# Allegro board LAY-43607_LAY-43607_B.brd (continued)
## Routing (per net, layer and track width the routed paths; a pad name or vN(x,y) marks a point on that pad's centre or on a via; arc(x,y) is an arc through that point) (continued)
USB2_RX_P: length 61.4
  BOTTOM w0.132: v1(73.83,54.6) 74.14,54.91 arc(74.23,54.97) 74.34,54.99 74.6,54.99 arc(74.62,54.99) 74.64,54.99 74.96,54.99 arc(75.17,55.03) 75.36,55.16 arc(75.47,55.33) 75.51,55.54 75.51,55.87 arc(75.55,55.96) 75.65,56 75.94,56 arc(76.07,56.06) 76.13,56.19 76.13,56.35 arc(76.07,56.48) 75.94,56.53 75.65,56.53 arc(75.55,56.57) 75.51,56.66 75.51,56.92 arc(75.56,57.14) 75.68,57.33 89.65,71.34 arc(89.7,71.39) 89.75,71.45 91.12,72.98 92.75,74.8 arc(93.27,75.58) 93.45,76.49 93.45,80.03 arc(93.79,81.61) 94.72,82.93 96,84.14 arc(96.22,84.43) 96.33,84.77 arc(96.86,89.67) 97,94.6 arc(97.01,94.67) 97.02,94.73 U44.1 U44.10 97.17,96.59 arc(97.17,96.64) 97.14,96.68 97.09,96.73 arc(97.06,96.77) 97.05,96.82 97.05,96.95 arc(97.41,98.6) 98.43,99.94 arc(99.33,100.55) 100.34,100.94 arc(100.72,101.1) 101.05,101.36 101.34,101.65 arc(101.53,101.96) 101.57,102.32 101.57,102.44 arc(101.61,102.53) 101.71,102.57 J70.15
USB2_TX_N: length 49
  TOP w0.132: U14.D2 72.89,55.52 arc(72.72,55.78) 72.66,56.08 72.66,56.32 arc(72.7,56.5) 72.82,56.65 73.01,56.82 80.43,63.11 arc(80.99,63.56) 81.58,63.98 85.74,66.74 arc(86.12,66.98) 86.51,67.2 87.66,67.8 arc(89.21,68.97) 90.3,70.58 99.24,89.97 arc(99.63,91.15) 99.74,92.39 arc(99.67,92.64) v2(99.5,92.83)
  BOTTOM w0.132: v2(99.5,92.83) C1326.1
USB2_TX_P: length 48.9
  TOP w0.132: v2(100.21,92.8) arc(100.04,92.63) 99.98,92.4 arc(99.87,91.1) 99.46,89.87 90.52,70.47 arc(89.39,68.8) 87.77,67.58 86.63,66.98 arc(86.24,66.77) 85.87,66.54 81.71,63.77 arc(81.14,63.36) 80.59,62.92 75.58,58.67 arc(75.53,58.59) 75.56,58.49 arc(75.59,58.4) 75.55,58.31 75.34,58.14 arc(75.25,58.11) 75.16,58.15 arc(75.07,58.2) 74.98,58.17 74.77,57.99 arc(74.73,57.9) 74.76,57.81 arc(74.79,57.72) 74.74,57.63 74.54,57.45 arc(74.44,57.42) 74.36,57.47 arc(74.27,57.51) 74.18,57.48 73.97,57.31 arc(73.92,57.22) 73.95,57.13 arc(73.98,57.03) 73.94,56.95 73.73,56.77 arc(73.64,56.74) 73.55,56.78 arc(73.46,56.83) 73.37,56.8 73.17,56.63 arc(73.04,56.43) U14.D1
  BOTTOM w0.132: v2(100.21,92.8) 100.19,92.83 C1325.1
USB2_UDM: length 67.8
  TOP w0.132: v2(99.64,98.83) 99.64,98.71 99.41,98.49 99.41,98.34 99.52,98.23 U552.3 ; v3(74.23,52.6) 73.83,52.2 U14.C6
  BOTTOM w0.132: J70.11 105.45,103.98 104.87,103.4 104.02,103.4 103.54,102.92 103.54,102.06 103.46,101.98 103.45,101.98 101.5,100.02 100.34,100.02 99.43,99.12 99.43,99.04 v2(99.64,98.83) 99.64,98.77 99.37,98.5 99.37,98.01 98.49,97.13 98.49,84.79 94.8,81.11 94.8,75.43 76.99,57.62 76.99,55.23 74.88,53.11 74.74,53.11 v3(74.23,52.6)
USB2_UDP: length 67.8
  TOP w0.132: U552.2 98.99,98.23 99.1,98.34 99.1,98.58 v2(98.85,98.83) ; U14.D6 73.03,52.2 v3(73.43,52.6)
  BOTTOM w0.132: J70.12 103.45,103.23 103.28,103.06 103.28,102.15 101.4,100.27 100.23,100.27 99.18,99.22 99.18,99.04 99.17,99.03 99.17,99.02 98.98,98.83 v2(98.85,98.83) 99.12,98.56 99.12,98.11 98.24,97.23 98.24,84.9 94.56,81.21 94.56,75.53 76.75,57.72 76.75,55.33 76.14,54.73 75.96,54.73 75.86,54.82 75.66,54.82 75.48,54.64 75.48,54.46 75.58,54.35 75.58,54.17 74.78,53.36 74.19,53.36 v3(73.43,52.6)
USB2_VBUS: length 6.6
  TOP w0.381: v3(74.23,51.79) 73.83,51.4 U14.C7 ; v2(78.36,54.57) 78.67,54.88 R255.2
  L4_INT_2 w0.254: v3(74.23,51.79) 77,54.57 v2(78.36,54.57)
USB3_ID: length 10.6
  TOP w0.137: U14.B5 75.02,53.4 76.16,53.4 80.53,57.77 v2(81.9,57.77)
  BOTTOM w0.137: v2(81.9,57.77) 81.6,57.47 81.6,57.31 81.61,57.31 81.61,57.11 81.59,57.09 R473.1
USB3_RESREF: length 12.2
  TOP w0.137: v3(71.03,53.39) 70.63,53 U14.G5
  L4_INT_2 w0.107: v3(71.03,53.39) 71.84,54.21 71.84,58.55 73.02,59.73 73.02,61.3 73.33,61.61 v2(73.33,62.02)
  BOTTOM w0.137: v2(73.33,62.02) 73.33,62.89 73.81,63.36 R474.1
USB3_VBUS: length 4.7
  TOP w0.381: U14.A7 75.43,51.4 v3(75.83,51.79) ; R471.1 v2(78.04,53.99)
  L4_INT_2 w0.254: v2(78.04,53.99) 76.15,52.1 76.13,52.1 v3(75.83,51.79)
USB_CONN_DM: length 10.5
  TOP w0.132: v2(118.48,8.78) 118.72,8.54 118.72,8.35 118.59,8.23 J58.2 ; U536.5 122.16,9.83 122.16,9.29 v2(122.41,9.03)
  L3_INT_1 w0.104: v2(118.48,8.78) 118.6,8.78 118.73,8.9 118.73,9.54 118.98,9.8 121.93,9.8 122.19,9.54 122.19,9.26 v2(122.41,9.03)
  BOTTOM w0.132: v2(118.48,8.78) 118.73,8.53 118.73,7.96 118.6,7.83 U537.3
USB_CONN_DP: length 10.5
  TOP w0.132: J58.3 119.24,8.23 119.08,8.38 119.08,8.57 v2(119.29,8.78) ; U536.4 121.91,9.87 121.91,9.24 v2(121.7,9.03)
  L3_INT_1 w0.104: v2(119.29,8.78) 119.11,8.78 118.98,8.91 118.98,9.44 119.09,9.54 120.57,9.54 120.68,9.44 120.68,9.27 120.78,9.16 120.99,9.16 121.09,9.27 121.09,9.44 121.2,9.54 121.83,9.54 121.93,9.44 121.93,9.26 v2(121.7,9.03)
  BOTTOM w0.132: v2(119.29,8.78) 118.98,8.48 118.98,7.98 119.14,7.83 U537.2
USB_CONN_PWR: length 15.1
  TOP w0.254: v2(117.94,10.43) J58.1 ; R849.2 125.72,12.72 v2(125.97,12.46)
  BOTTOM w0.254: U537.4 117.84,9.87 117.84,10.33 v2(117.94,10.43) 117.94,11.04 118.6,11.7 118.98,11.7 120.25,12.97 125.46,12.97 v2(125.97,12.46)
VSNVS: length 2.1
  TOP w0.254: v4(71.81,82.41) 72.1,82.12 U561.47
  BOTTOM w0.254: v4(71.81,82.41) 72.12,82.1 C1550.1
N18041442: length 71.3
  L3_INT_1 w0.107: v2(114.84,21.39) 114.54,21.68 v2(114.54,29.58)
  L4_INT_2 w0.107: v2(114.54,29.58) 114.22,29.9 114.22,30.25 103.77,40.71 103.77,41.19 100.73,44.23 100.73,50.26 100.85,50.37 100.85,50.38 101.82,51.35 101.82,55.69 105.17,59.05 105.17,61.74 105.52,62.09 105.52,62.1 105.59,62.17 105.59,66.04 v2(105.25,66.37)
  BOTTOM w0.137: v2(105.25,66.37) 104.83,66.37 104.61,66.6 103.46,66.6 101.95,68.1 U547.4 101.52,68.5 100.32,69.71 100.32,70.25 U535.2 ; R304.2 122.73,21.39 v2(114.84,21.39)
  BOTTOM w0.381: R304.2 123.04,22.33 U55.6
N26524532: length 15.5
  TOP w0.137: U530.2 100.66,88.73 100.92,88.99 v2(101.53,88.99) ; U40.A2 111.59,91.55 111.37,91.33 v2(111.21,91.33)
  L3_INT_1 w0.107: v2(101.53,88.99) 101.99,88.54 v2(104.91,88.54)
  L4_INT_2 w0.107: v2(104.91,88.54) 107.71,91.33 v2(111.21,91.33)
  BOTTOM w0.137: R245.2 v2(101.53,88.99)
N26564824: length 2.2
  TOP w0.124: U123.D16 43.55,71.91 arc(43.46,71.77) 43.43,71.6 43.43,70.39 arc(43.47,70.19) 43.58,70.03 C847.2
N26564835: length 2.2
  TOP w0.124: U123.D15 42.98,71.91 arc(43.07,71.77) 43.11,71.6 43.11,70.39 arc(43.07,70.19) 42.95,70.03 C848.2
N26564871: length 3.6
  TOP w0.124: C849.2 38.47,69.11 38.47,69.98 38.33,70.12 38.33,70.48 38.47,70.62 38.47,71.32 39.04,71.89 U123.D11
N26564875: length 3.7
  TOP w0.124: U123.D12 39.42,71.68 39.31,71.68 39.25,71.63 39.23,71.63 38.79,71.19 38.79,69.11 C850.2
N26565200: length 4.4
  TOP w0.094: 35.67,72.72 36.04,72.72 36.35,73.02
  TOP w0.137: 36.35,73.02 U123.B7 ; 35.67,72.72 34.39,72.72 R653.2 v2(34.51,73.25)
  BOTTOM w0.381: R653.2 v2(34.51,73.25)
N26565210: length 2.9
  TOP w0.137: U123.B8 35.26,72.37 35.11,72.23 R652.2
N26565245: length 4.4
  TOP w0.094: U123.D8 36.49,74.32 36.23,74.06 35.75,74.06 35.67,73.99
  TOP w0.137: R655.1 34.38,74.26 34.65,73.99 35.67,73.99
N26565259: length 3.9
  TOP w0.094: 35.67,74.33 36.14,74.33 36.46,74.65 U123.C7
  TOP w0.137: 35.67,74.33 35.11,74.33 34.29,75.15 R661.1
N26565267: length 4.4
  TOP w0.137: C693.1 42.53,82.33 42.62,82.25 U123.A7
N26565570: length 3.8
  TOP w0.137: U123.C10 36.99,71.72 35.88,71.72 35.46,71.31 34.47,71.31 34.37,71.21 R660.1
N26565580: length 1.8
  TOP w0.094: 47.67,75.95 U123.C19
  TOP w0.137: 47.67,75.95 47.73,75.89 R657.1
N26565586: length 1.3
  TOP w0.137: R658.1 47.75,76.75 U123.B12
N26565592: length 2.7
  TOP w0.094: 47.5,76.99 47.43,76.92 U123.D26
  TOP w0.137: R659.1 47.98,77.25 47.76,77.25 47.5,76.99
N26602439: length 22.8
  BOTTOM w0.137: P1.7 48.58,105.1 52.06,101.62 57.72,101.62 61.9,97.43 61.9,97.23 C772.1
N26602442: length 16.6
  BOTTOM w0.137: C1021.1 56.5,103.52 53.42,103.52 P1.12
N26602445: length 15.2
  BOTTOM w0.137: P1.4 56.63,105.86 56.63,104.28 C1022.1
N26602448: length 13.2
  BOTTOM w0.137: C1023.1 64.25,101.96 59.95,106.26 58.47,106.26 P1.9
N26631448: length 5.1
  TOP w0.137: 62.9,87.9 C1140.1 62.9,89.4 61.16,91.14 P1.31
N26631451: length 4
  TOP w0.137: R644.2 47.49,87.78 C1139.1 47.49,89.51 P1.34
N26631860: length 4.6
  TOP w0.137: R645.2 C1142.1 63.45,116 P1.27
N26631884: length 8.1
  TOP w0.137: R646.2 C1141.1 44.82,112.88 47.94,116 P1.30
N26633114: length 5.7
  BOTTOM w0.137: C1024.2 63.31,93.87 60.58,96.6 P1.14
N26633139: length 7.9
  BOTTOM w0.137: P1.22 59.07,93.46 61.46,93.46 62.83,92.09 C1143.2
N26633162: length 11.5
  BOTTOM w0.137: C1144.2 63.05,92.98 59.95,96.08 55.99,96.08 P1.17
N26633185: length 14.2
  BOTTOM w0.137: P1.25 53.55,92.98 61.36,92.98 63.14,91.2 C1145.2
N26633865: length 20.9
  BOTTOM w0.137: C1146.2 22.45,107.55 29.58,100.42 34.35,100.42 P2.14
N26633881: length 20.4
  BOTTOM w0.137: C1147.2 22.58,106.68 29.83,99.43 32.89,99.43 34.29,98.04 P2.22
N26633897: length 14.2
  BOTTOM w0.137: P2.17 22.97,105.8 C1148.2
N26633913: length 14.9
  BOTTOM w0.137: C1149.2 20.92,105.28 22.6,105.28 28.29,99.59 P2.25
N26633941: length 11.6
  TOP w0.137: P2.27 35.6,114.36 35.6,111.63 36.46,110.76 C1150.1 R647.2
N26633965: length 4.9
  TOP w0.137: P2.30 24.38,116 23.97,115.59 C1151.1 21.58,115.56 R648.2
N26634920: length 4.9
  BOTTOM w0.137: C1152.1 21.09,107.9 P2.7
N26634936: length 11.2
  BOTTOM w0.137: C1153.1 27.51,109.31 28.29,108.53 P2.12
N26634952: length 11.7
  BOTTOM w0.137: P2.4 29,110.18 C1154.1
N26634968: length 17.9
  BOTTOM w0.137: C1155.1 20.92,110.7 32.12,110.7 34.29,108.53 P2.9
N26634994: length 3.7
  TOP w0.137: P2.31 35.04,89.43 C1157.1 R649.2
N26635018: length 5.5
  TOP w0.137: R650.2 C1156.1 23.35,90.75 23.74,91.14 P2.34
N26645840: length 2.2
  TOP w0.137: v2(19.88,48.4) 19.88,48.39 R669.1
  BOTTOM w0.137: J46.56 v2(19.88,48.4)
N26649122: length 1.9
  TOP w0.254: R922.1 36.28,47.44 35.79,47.44 v2(35.57,47.67)
  BOTTOM w0.254: v2(35.57,47.67) 35.79,47.44 D510.A
N26756957: length 2.8
  TOP w0.137: v2(18.74,78.25) 19.26,77.73 TP127.1
  BOTTOM w0.137: U523.6 17.44,79.03 18.51,79.03 18.74,78.79 v2(18.74,78.25)
N26760872: length 2.3
  TOP w0.137: v2(103.87,82.67) 104.13,82.41 U524.7
  BOTTOM w0.137: v2(103.87,82.67) 104.1,82.44 R745.1
N26860199: length 13.8
  TOP w0.137: v2(29.14,36.07) J52.56
  L3_INT_1 w0.107: v2(29.14,36.07) 29.55,35.66 30.69,35.66 33.65,38.62 36.37,38.62 37.75,37.25 v2(38.95,37.25)
  BOTTOM w0.137: v2(38.95,37.25) 38.44,37.76 R801.1
N26860244: length 1.1
  TOP w0.137: R923.1 41.59,35.22 D511.A
N26874475: length 5.4
  TOP w0.137: v2(24.55,85.7) 24.89,85.36 J15.9
  BOTTOM w0.137: v2(24.55,85.7) 24.25,85.4 22.1,85.4 R188.2
N26911462: length 3.3
  TOP w0.137: R401.2 71.56,114.58 J56.1
N26937676: length 2
  TOP w0.137: U538.1 v2(110.17,63.17)
  BOTTOM w0.137: R857.2 109.39,63.17 v2(110.17,63.17)
N26937874: length 1.5
  TOP w0.137: U538.5 105,65.45 v2(105,65.76)
  BOTTOM w0.137: v2(105,65.76) 105.18,65.58 R858.1
N26987601: length 6.4
  TOP w0.137: R870.1 53.51,54.06 53.56,54.06 U14.AH4
N27008437: length 7.4
  TOP w0.137: U14.AG2 54.41,55.4 53.44,56.36 53.11,56.36 R874.1
N27008440: length 8.6
  TOP w0.137: U14.AF2 55,55.82 54.39,55.82 50.08,60.13 50.08,60.28 R875.1
N27027375: length 10.6
  TOP w0.137: U551.2 v2(103.29,85.11) ; v2(103.87,91.08) 104.72,91.08 104.89,91.25 U550.A2
  L4_INT_2 w0.107: v2(103.29,85.11) 103.29,89.35 102.98,89.66 102.98,90.59 103.46,91.08 v2(103.87,91.08)
  BOTTOM w0.137: v2(103.29,85.11) 103.29,86.02 103.16,86.14 R878.2
N27121803: length 0.9
  TOP w0.137: R67.2 C128.1
N27124315: length 29
  TOP w0.254: R888.2 122.64,54.02 TP116.1
  L4_INT_2 w0.381: v5(103.24,48.6) 108.7,48.6 109.08,48.98 109.08,54.47 110.45,55.84 119.84,55.84 120.58,55.09 TP116.1
  BOTTOM w0.508: R890.2 v5(103.24,48.6)
N27124319: length 29.7
  TOP w0.254: R889.1 122.67,55.45 122.22,55.9 TP117.1
  L4_INT_2 w0.381: TP117.1 120.86,56.44 110.17,56.44 108.43,54.7 108.43,49.6 108.05,49.22 107.25,49.22 107.23,49.2 106.71,49.2 106.69,49.22 102.33,49.22 101.87,48.76 v5(101.87,48.6)
  BOTTOM w0.508: R890.3 v5(101.87,48.6)
N27157188: length 4.1
  TOP w0.137: R902.1 115.92,73.85 C1341.2
  TOP w0.254: U560.24 117.48,71.61 116.88,72.22 R900.2 115.9,73.04 C1341.2
N27157490: length 3.7
  TOP w0.254: R903.1 120.15,72.49 121.09,71.55 121.09,70.48 120.96,70.36 U560.18
N27163263: length 2.3
  TOP w0.254: U560.21 118.98,71.61 119.18,71.81 C1344.1
N27259526: length 44.6
  L4_INT_2 w0.107: v2(104.62,85.22) 104.99,85.59 104.99,86.15 104.5,86.64 104.5,88.91 112.67,97.08 112.67,105.04 D509.1
  BOTTOM w0.137: R924.1 98.21,74.34 98.59,74.72 98.59,75.92 98.8,76.13 98.8,76.62 102.47,80.3 102.47,83.08 v2(104.62,85.22)
N27259549: length 9.8
  BOTTOM w0.137: R925.1 114.84,101.83 114.84,109.74 D509.3
N27260803: length 67.5
  TOP w0.137: v2(126.04,27.72) 125.13,26.81 122.54,26.81 122.49,26.87 122.33,26.87 121.4,27.8 121.4,28.39 121.13,28.66 120.9,28.66 120.4,29.17 U562.4 ; v2(98.61,66.95) 99.33,66.95 R940.2
  L3_INT_1 w0.107: v2(126.04,27.72) 126.04,28.13 126.11,28.21 126.11,28.22 126.58,28.68 126.58,29.4 125.57,30.42 125.57,50.1 120.15,55.51 120.15,57.75 118.18,59.73 117.93,59.73 113.88,63.77 110.65,63.77 109.68,64.74 107.01,64.74 106.58,65.17 104.19,65.17 103.2,66.15 99.41,66.15 v2(98.61,66.95)
  BOTTOM w0.137: U547.1 98.75,66.8 v2(98.61,66.95)
N27955896: length 2.3
  TOP w0.254: v4(76.32,79.42) 76.19,79.28 74.79,79.28 U561.39
  BOTTOM w0.254: R931.1 v4(76.32,79.42)
N27955915: length 2.3
  TOP w0.254: U561.52 69.6,82.74 69.96,83.1 R932.1
N27960172: length 3.1
  TOP w0.254: U561.20 70.1,72.11 69.45,71.47 R935.2
N27963255: length 2.1
  TOP w0.254: U561.15 67.6,73.27 67.07,72.74 C1552.1
N27963260: length 2.2
  TOP w0.254: C1553.1 69.1,72.35 U561.18
N27963345: length 3.2
  TOP w0.254: U561.25 72.6,72.15 73.34,71.41 C1554.1
N27963673: length 2.2
  TOP w0.254: R937.2 73.61,83.53 73.61,82.32 73.6,82.31 U561.44
N28073320: length 1.6
  TOP w0.137: U561.14 66.61,74.26 66.37,74.03 66.12,74.03 R943.1
N28144784: length 3.6
  TOP w0.137: U536.9 123.47,11.77 123.79,12.09 123.79,13.01 R944.2
N28148907: length 1.3
  TOP w0.137: U536.13 121.8,14.14 R840.1
N28150385: length 1.2
  TOP w0.137: U536.15 120.8,13.79 120.79,13.8 R843.2
N28196038: length 3.3
  TOP w0.137: U565.E2 67.88,15.31 68.57,15.31 69.64,16.37 v1(70.18,16.37)
N28196089: length 1.5
  TOP w0.137: v2(70.81,18.4) 71.1,18.11 U565.A7
  BOTTOM w0.137: v2(70.81,18.4) 70.75,18.46 R83.2
N28196104: length 0.8
  TOP w0.137: U565.B7 71.1,17.31 v1(70.81,17.6)
N28245014: length 12.8
  BOTTOM w0.137: D509.5 114.41,111.86 R948.1
N28345649: length 0.6
  TOP w0.137: v1(64.63,39.8) 65.02,40.2 U14.P21
N28397648: length 16.2
  TOP w0.305: Q3.3 84.32,60.71 84.32,62.26 89.92,67.87 R947.2
N29074387: length 12
  TOP w0.124: U14.AG10 54.36,49.26 arc(54.26,49.33) 54.14,49.35 53.68,49.35 53.64,49.32 44.01,49.32 43.79,49.09 43.2,49.09 C1582.2
N29074390: length 11.9
  TOP w0.124: C1583.2 43.2,48.77 43.92,48.77 44.15,49 50.18,49 arc(50.27,48.96) 50.31,48.86 arc(50.35,48.77) 50.44,48.73 50.67,48.73 arc(50.77,48.77) 50.81,48.86 arc(50.84,48.96) 50.94,49 51.17,49 arc(51.26,48.96) 51.3,48.86 arc(51.34,48.77) 51.43,48.73 51.67,48.73 arc(51.76,48.77) 51.8,48.86 arc(51.84,48.96) 51.93,49 52.17,49 arc(52.26,48.96) 52.3,48.86 arc(52.34,48.77) 52.43,48.73 52.67,48.73 arc(52.76,48.77) 52.8,48.86 arc(52.83,48.96) 52.93,49 U14.AH10
N271624620: length 0.9
  TOP w0.254: C1343.1 117.41,75.18 R905.2

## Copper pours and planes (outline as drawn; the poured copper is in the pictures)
1V0_F104 on TOP: 32.6,79.7 32.4,79.7 32.33,79.63 32.33,76.64 32.52,76.45 34.07,76.45 34.38,76.75 34.38,79.44 34.15,79.67 32.62,79.67
1V0_F104 on TOP: 57.72,85.51 57.72,82.21 57.77,82.16 61.28,82.16 61.71,82.59 61.71,86.02 61.4,86.33 58.13,86.33 57.69,85.89 57.69,85.53
1V0_F104 on BOTTOM: 32.81,79.37 32.54,79.09 32.54,76.8 32.89,76.45 34.07,76.45 34.38,76.75 34.38,78.86 33.86,79.37
1V0_F104 on L3_INT_1: 58.37,86.35 58.37,82.74 61.41,79.71 64.77,79.71 65.19,79.29 66.99,79.29 67.46,79.75 67.46,83.74 64.63,86.57 58.59,86.57
1V0_F104 on L4_INT_2: 61.88,86.5 62.04,86.35 62.04,83.38 61.1,82.44 52.93,82.44 52.92,82.43 52.76,82.59 51.32,82.59 51.32,82.4 51.62,82.1 51.62,79.04 51.1,78.52 48.33,78.52 47.13,77.31 45.65,77.31 45.65,72.54 45.27,72.17 33.9,72.17 32.75,73.32 32.75,79.57 33.85,80.66 36.2,80.66 36.93,81.39 36.93,82.61 40.04,85.72 49.26,85.72 50.05,86.5
1V0_QSG on TOP: 32.17,80.71 32.29,80.59 33.56,80.59 33.82,80.84 33.82,86.43 33.39,86.86 32.4,86.86 32.17,86.63
1V0_QSG on BOTTOM: 32.17,80.71 32.29,80.59 33.56,80.59 33.82,80.84 33.82,86.43 33.51,86.73 32.27,86.73 32.17,86.63
1V0_QSG on L5_PWR: 32.74,77.6 34.43,75.91 34.43,74.9 34.97,74.35 34.97,70.57 35.16,70.38 35.72,70.38 36.36,71.01 46.95,71.01 47.58,71.65 47.58,80.51 46.9,81.2 37.5,81.2 34.33,84.37 34.33,84.94 33.97,85.3 33.03,85.3 32.74,85.01
1V35 on TOP: 57.92,76.37 57.92,72.33 57.93,72.33 58.79,71.47 60.99,71.47 61.45,71.93 61.45,76.78 61.4,76.78 61.36,76.81 58.37,76.81
1V35 on TOP: 46.09,52.19 46.09,50.53 45.56,50.01 41.75,50.01 41.75,52.88 41.87,53 44.83,53 44.85,53.02 45.25,53.02
1V35 on L4_INT_2: 53.91,68.8 58.41,73.3 58.49,73.3 58.49,76.44 58.67,76.62 65.49,76.62 66.08,76.04 66.08,73.93 66.03,73.88 66.03,73.68 65.56,73.21 65.55,73.21 65.55,68.91 65.39,68.75 65.37,68.78 65.35,68.78 65.35,68.35 65.11,68.11 65.1,68.13 60.14,68.13 58.39,66.38 55.77,66.38 53.48,64.09 47.97,64.09 41.82,57.93 41.82,53.33 42.13,53.02 42.69,53.02 42.94,52.77 42.94,50.44 42.54,50.04 40.17,50.04 39.67,50.55 39.67,62.75 41.56,64.64 41.6,64.64 44.43,67.47 52.95,67.47 53.16,67.69 53.61,67.69 53.91,67.98
2V5 on TOP: 40.68,20.57 40.68,17.7 41.21,17.16 44.02,17.16 44.02,17.42 42.83,18.61 42.83,20.57 52.49,20.57 52.49,17.67 52.92,17.24 54.9,17.24 54.92,17.26 55.1,17.08 55.3,17.08 55.43,17.21 55.43,17.4 55.13,17.71 55.13,19.58 54.52,20.18 54.52,20.57 61.28,20.57 64.7,17.14 66.79,17.14 66.79,18.94 65.69,20.03 64.65,20.03 62.32,22.37 35.14,22.37 35.14,20.72 35.29,20.57
2V5 on TOP: 80.25,82.16 83.55,82.16 84.01,81.7 84.01,78.58 83.6,78.17 80.4,78.17 80.1,78.48 80.1,82.01
2V5 on TOP: 48.88,78.1 48.88,74.72 50.48,74.72 50.48,78.1
2V5 on TOP: 49.79,84.62 49.79,88.82 50.02,89.04 51.6,89.04 51.83,88.82 51.83,84.6 51.75,84.52 49.9,84.52
2V5 on BOTTOM: outline of 107 points within 28,51.43 83.6,90.16
2V5 on L3_INT_1: 38.63,6.51 42.78,2.35 43.75,2.35 43.76,2.37 44.5,2.37 44.51,2.35 85.66,2.35 85.84,2.53 85.84,2.99 85.63,3.19 76.95,3.19 76.77,3.01 71.71,3.01 71.33,3.4 64.98,3.4 64.6,3.01 56.27,3.01 55.29,4 54.17,4 54.17,6.35 52.94,7.59 49.98,7.59 49.73,7.34 49.73,6.67 49.9,6.49 52.23,6.49 53.14,5.59 53.14,3.73 53.11,3.7 45.02,3.7 41.23,7.48 41.23,21.1 39.84,22.5 35.49,22.5 35.19,22.19 35.19,20.82 35.62,20.39 38.87,20.39 39.48,19.78 39.48,10.99 38.63,10.14
2V5 on L3_INT_1: 38.63,6.51 42.78,2.35 43.75,2.35 43.76,2.37 44.5,2.37 44.51,2.35 85.66,2.35 85.84,2.53 85.84,2.99 85.63,3.19 76.95,3.19 76.77,3.01 71.71,3.01 71.33,3.4 64.98,3.4 64.6,3.01 56.27,3.01 55.59,3.7 45.02,3.7 41.23,7.48 41.23,21.1 39.84,22.5 35.49,22.5 35.19,22.19 35.19,20.82 35.62,20.39 38.87,20.39 39.48,19.78 39.48,10.99 38.63,10.14
2V5 on L4_INT_2: 29.55,92.37 22.11,92.37 21.07,91.34 21.07,77.53 17.8,74.25 17.8,58.82 18.78,57.84 18.78,53.48 17.89,52.6 17.8,52.6 17.8,47.52 19.42,45.9 19.42,40.75 17.8,39.13 17.8,17.03 19.94,14.9 34.96,14.9 35.63,15.57 35.63,20.36 38.29,20.36 38.77,20.85 38.77,21.66 36.42,24.01 33.14,24.01 32.37,24.78 28.05,24.78 26.91,25.93 26.84,25.93 24.86,27.91 24.86,50.18 27.04,52.36 27.04,57.8 26.02,58.82 26,58.82 24.86,59.96 24.86,85.76 27.3,88.21 29.8,88.21 29.96,88.36 29.96,91.97 ; 1 cut-out
2V5_QSG on TOP: 50,83.1 50,78.4 50.15,78.25 50.63,78.25 50.63,75.96 50.84,75.76 51.8,75.76 51.84,75.8 51.84,82.76 51.88,82.8 51.88,83.35 51.83,83.41 50.3,83.41
2V5_QSG on L4_INT_2: 40.35,81.14 40.35,78.3 40.98,77.67 47.36,77.67 48.35,78.66 51.04,78.66 51.55,79.16 51.55,81.63 51.12,82.06 41.26,82.06
3V3 on TOP: 15.83,37.89 33.28,37.89 33.79,37.38 33.79,37.05 40.46,37.05 40.72,36.79 40.72,35.06 40.47,34.82 35.62,34.82 34.73,33.93 33.11,33.93 32.93,34.1 32.93,36.11 32.34,36.69 16.6,36.69 16.32,36.42 16.32,33.6 16.14,33.42 14.41,33.42 14.03,33.8 14.03,35.83 14.41,36.21 15.4,36.21 15.4,36.24 15.53,36.36 15.53,37.58
3V3 on TOP: 122.64,9.19 123.11,8.72 126.57,8.72 126.88,9.03 126.88,9.81 126.82,9.87 125.8,9.87 125.73,9.94 123.92,9.94 123.65,10.21 123.65,10.88 123.61,10.93 122.68,10.93 122.64,10.89
3V3 on TOP: 79.44,118.13 79.44,113.81 79.51,113.73 82.54,113.73 82.55,113.72 82.85,113.72 83.12,113.45 83.12,111.4 82.97,111.24 82.48,111.24 82.43,111.29 82.43,112.79 82.33,112.89 79.77,112.89 79.64,112.77 79.64,111.45 79.46,111.27 77.58,111.27 77.4,111.45 77.4,112.82 77.33,112.89 75.02,112.89 74.89,112.77 74.89,111.29 74.76,111.17 73.67,111.17 73.57,111.27 73.57,113.61 73.7,113.73 77.81,113.73 77.96,113.89 77.96,119.52 78.09,119.65 79.36,119.65 79.74,119.27 79.74,118.38 79.49,118.13
3V3 on TOP: 97.83,64.52 97.83,64.52 100.47,64.52 100.61,64.66 100.61,65.35 100.64,65.37 101.98,65.37 102.67,66.06 102.67,66.88 102.27,67.28 101.48,67.28 101.39,67.19 101.38,67.19 101.38,66.52 101.17,66.31 98.32,66.31 97.98,65.97 96.38,65.97 95.18,67.17 93.25,67.17 93.07,66.99 93.07,66.21 93.4,65.88 93.98,65.88 95.33,64.52
3V3 on TOP: 110.42,61.35 110.42,57.62 128.11,57.62 128.89,56.84 131.58,56.84 131.58,61.35 114.89,61.35 114.76,61.22 114.76,61.22 113.47,61.22 113.34,61.35
3V3 on TOP: 13.86,45.12 13.24,45.74 13.24,47.62 13.24,47.63 13.24,48.53 13.88,49.17 16.24,49.17 17.61,47.79 28.47,47.79 29.06,47.21 31.07,47.21 31.74,47.87 31.74,50.56 31.99,50.82 33.13,50.82 33.64,50.31 33.64,48.3 34.72,48.3 34.99,48.03 34.99,46.77 34.83,46.61 32.21,46.61 31.38,45.78 18.07,45.78 17.42,45.14 15.59,45.14 15.58,45.12
3V3 on BOTTOM: 79.46,115.13 79.26,114.93 78.55,114.93 78.5,114.98 78.5,116.93 78.37,117.06 78.37,118.58 77.91,119.04 77.91,119.42 78.06,119.58 79.21,119.58 79.46,119.32
3V3 on BOTTOM: 32.75,46.28 34.8,46.28 35.01,46.49 35.01,48.14 34.64,48.51 32.88,48.51 32.71,48.35 32.71,46.31
3V3 on BOTTOM: 126.91,24.44 126.91,27.17 125.53,27.17 125.53,24.44
3V3 on BOTTOM: 110.41,59.58 110.41,56.81 125.98,56.81 126.93,55.86 130.62,55.86 131.57,56.81 131.57,61.32 110.41,61.32 108.74,62.98 108.74,63.53 108.71,63.56 107.96,63.56 107.89,63.49 107.89,62.96 107.63,62.7 106,62.7 106,63.21 105.45,63.77 104.76,63.77 104.75,63.76 101.85,63.76 99.56,61.46 96.34,61.46 96.38,61.42 95.74,61.42 95.29,60.97 95.29,60.08 95.28,60.07 91.01,60.07 90.94,60 90.75,60 90.66,59.91 90.66,59.26 90.74,59.18 91.48,59.18 91.53,59.23 92.25,59.23 92.61,58.87 92.61,58.72 94.15,58.72 94.45,58.41 94.45,57.25 94.1,56.9 94.09,56.9 93.77,56.58 93.77,55.46 94.05,55.17 95.36,55.17 96.36,56.17 97.95,56.17 99.02,57.24 99.02,58.53 99.03,58.53 102.14,61.64 104.23,61.64 105.01,60.85 105.98,60.85 106.01,60.88 109.11,60.88
3V3 on BOTTOM: 35.85,35.04 35.95,34.95 40.54,34.95 40.57,34.98 40.57,35.41 39.43,36.56 39.04,36.56 38.58,37.01 38.58,37.03 36.2,37.03 35.85,36.67
3V3 on BOTTOM: 20.11,61.13 20.17,61.06 21.37,61.06 21.49,61.19 21.49,62.71 21.01,63.2 21.01,67.16 21.04,67.18 21.04,67.95 21.47,67.95 21.57,68.05 21.57,69.12 21.55,69.13 21.55,69.76 21.27,70.05 19.52,70.05 19.18,69.71 19.18,61.67 19.77,61.09 20.07,61.09
3V3 on BOTTOM: 71.05,81.3 68.03,81.3 68.01,81.32 67.12,80.43 67.12,74.85 68.31,73.65 74.69,73.65 75.12,74.08 75.12,75.3 75.45,75.63 75.45,76.05 74.61,76.89 74.61,78.55 74.66,78.6 75.01,78.6 75.23,78.38 75.23,77.88 75.3,77.81 76.49,77.81 76.67,77.99 76.67,78.63 76.77,78.73 77.28,78.73 77.35,78.66 77.35,72.94 76.41,72 65.09,72 64.32,72.76 64.32,82.11 65.57,83.35 71.41,83.35 71.44,83.33 71.44,81.68
3V3 on BOTTOM: 86.52,87.55 86.52,86.15 91.91,86.15 91.91,87.55
3V3 on BOTTOM: 13.66,44.85 17.29,44.85 17.56,45.13 17.56,45.9 17.41,46.05 16.26,46.05 16.04,46.26 16.04,48.6 15.96,48.69 13.78,48.69 13.48,48.39 13.48,45.03
3V3 on L5_PWR: 13.88,2.33 13.88,45.05 13.83,45.1 13.83,45.38 13.47,45.74 13.47,47.87 13.88,48.28 13.88,56.28 13.32,56.84 13.32,65.88 13.88,66.44 13.88,119.72 13.95,119.79 131.3,119.79 131.3,2.31 123.94,2.31 123.94,5.22 123.48,5.96 122.67,6.24 115.81,6.24 114.9,5.79 114.54,4.84 114.54,2.31 13.9,2.31
5V0 on TOP (solid shape): 115.07,93.16 115.07,90.37 115,90.29 114.82,90.29 113.55,90.29 113.42,90.29 113.27,90.14 113.27,90.11 113.02,89.86 110.88,89.86 110.6,89.58 110.6,89.12 110.28,89.12 110.28,87.85 110.6,87.85 110.6,85.97 110.45,85.82 105.37,85.82 105.29,85.89 105.29,86.17 105.27,86.2 105.27,88.52 105.27,88.59 105.52,88.59 105.95,89.02 105.95,91.41 105.57,91.79 105.54,91.79 105.51,91.81 105.51,91.84 105.54,91.96 105.52,92.08 105.52,92.26 105.54,92.34 105.53,92.43 105.63,92.52 105.98,92.52 106.23,92.78 107.33,92.78 107.35,92.8 108.72,92.8 109,92.52 109,91.51 109.31,91.2 110.88,91.2 110.89,91.18 111.21,90.97 111.53,91.18 111.55,91.2 111.66,91.2 111.67,91.18 112.17,91.02 112.28,91.54 112.28,92.73 112.33,92.73 112.33,93.18 112.39,93.25 114.98,93.25
5V0 on BOTTOM: 110.51,89.39 110.51,85.83 110.47,85.79 105.46,85.79 104.94,86.32 104.94,89.43 104.97,89.46 110.45,89.46
5V0 on L3_INT_1: 89.81,96.11 90.45,95.47 96.51,95.47 98.44,97.4 103.13,97.4 104.84,95.7 104.84,91.05 105.29,90.59 105.29,84.19 107.73,81.75 118.98,81.75 119.37,82.14 119.37,83.68 118.07,84.98 110.25,84.98 109.31,85.92 109.31,98.19 107.15,100.35 104.51,100.35 104.02,100.83 90.49,100.83 89.81,100.16
12V0 on TOP: 118.48,32.02 118.48,30.12 127.24,30.12 127.37,30.24 127.49,30.24 127.62,30.37 127.62,33.42 126.73,34.31 125.08,34.31 124.57,33.8 124.57,32.66 123.94,32.02
12V0 on TOP: 123.75,98.54 123.75,96.66 123.75,96.65 123.75,91.16 123.75,91.16 123.75,90.9 124.24,90.41 124.24,85.4 124.99,84.65 126.96,84.65 127.76,83.85 127.76,81.07 128.66,80.18 128.66,78.99 129.02,78.63 129.02,78.03 129.05,78 129.05,77.82 128.64,77.41 121.98,77.41 121.98,77.41 121.53,77.86 121.53,83.2 121.53,83.2 121.53,83.45 118.17,86.81 118.04,86.81 115.71,89.15 115.71,98.44 115.81,98.54
12V0 on BOTTOM: 123.73,98.67 123.73,96.63 123.73,90.95 125.15,89.54 125.15,81.69 125.32,81.52 128.1,81.52 128.16,81.46 128.16,79.46 128.86,78.76 128.86,77.51 128.74,77.38 121.97,77.38 121.97,77.38 121.6,77.75 121.6,83.33 115.73,89.2 115.73,98.67
12V0 on BOTTOM: 118.46,31.99 118.46,30.09 127.22,30.09 127.35,30.21 127.48,30.21 127.61,30.34 127.61,33.39 126.72,34.28 125.07,34.28 124.56,33.77 124.56,32.63 123.92,31.99
12V0 on L4_INT_2: 116.09,100.42 131.3,100.42 131.3,29.76 130.03,29.76 130.03,29.58 129.68,29.23 119.03,29.23 118.43,29.84 118.43,32.25 118.7,32.53 118.7,33.68 125.07,40.05 125.07,60.86 119.95,65.98 119.95,85.84 119.29,86.5 116.09,86.5
12V0_FILTERED_PS_V1V0 on TOP: 119.44,46.3 119.44,47.87 119.05,48.26 119.05,52.15 119.37,52.47 122.41,52.47 122.92,51.96 122.92,49.17 122.16,48.4 121.63,48.4 120.74,47.52 120.74,46.9 120.76,46.88 120.76,46.3
12V0_FILTERED_PS_V1V0 on TOP: 118.91,42.38 118.91,38.32 120.25,36.97 120.25,34.82 120.51,34.56 124.7,34.56 125.59,35.45 125.59,38.37 124.45,39.51 121.84,39.51 121.84,41.86 120.75,42.96 120.75,43.82 120.76,43.83 120.76,44.37 119.52,44.37 119.52,42.99
12V0_FILTERED_PS_V1V0 on BOTTOM: 118.89,42.36 118.89,38.29 120.24,36.95 120.24,34.79 120.49,34.53 124.68,34.53 125.57,35.42 125.57,38.34 124.43,39.49 121.83,39.49 121.83,41.84 120.73,42.93 120.73,43.79 120.75,43.8 120.75,44.34 119.5,44.34 119.5,42.97
12V0_FILTERED_PS_V1V0 on BOTTOM: 119.43,46.27 119.43,47.84 119,48.27 119.03,48.3 119.03,52.12 119.35,52.44 122.4,52.44 122.91,51.93 122.91,49.14 122.14,48.38 121.62,48.38 120.73,47.49 120.73,46.87 120.75,46.85 120.75,46.27
12V0_FILTERED_PS_V1V0 on L4_INT_2: 118.17,49.19 119.01,48.35 119.01,42.66 118.65,42.31 118.65,40.33 118.81,40.17 121.73,40.17 121.96,40.4 121.96,42.46 120.41,44.01 120.41,47.46 120.81,47.87 122.44,47.87 122.54,47.97 122.54,51.6 121.83,52.32 118.88,52.32 118.6,52.04 118.6,51.33 118.17,50.89
12V0_FILTERED_PS_V3V3 on TOP: 120.24,69.03 120.24,67.74 120.3,67.69 121.69,67.69 122.57,66.8 130.25,66.8 130.73,67.28 130.73,70.77 130.34,71.16 126.58,71.16 126.24,70.83 126.24,69.31 125.96,69.03
12V0_FILTERED_PS_V3V3 on TOP: 116.25,69.01 117.15,69.01 117.26,68.9 117.26,67.76 117.17,67.68 116.45,67.68 116.34,67.57 116.34,66.82 115.2,65.67 112.72,65.67 112.41,65.97 112.41,67.65 112.68,67.92 115.17,67.92 115.38,68.13 115.38,68.41 115.56,68.58 115.83,68.58
12V0_FILTERED_PS_V3V3 on BOTTOM: 115.99,68.65 116.95,68.65 116.98,68.62 116.98,67.44 115.39,65.85 112.76,65.85 112.58,66.03 112.58,67.66 112.81,67.89 115.23,67.89
12V0_FILTERED_PS_V3V3 on BOTTOM: 120.41,68.7 120.41,67.68 120.43,67.66 121.68,67.66 122.56,66.78 130.24,66.78 130.54,67.08 130.54,73.52 130.13,73.93 126.5,73.93 126.45,73.88 126.45,68.72 126.43,68.7
12V0_FILTERED_PS_V3V3 on L5_PWR: 112.05,68.7 112.05,65.68 129.1,65.68 129.1,65.69 129.93,66.52 129.93,70.83 129.25,71.52 129.22,71.49 122.11,71.49 122.11,75.63 118.5,75.63 118.5,68.83 118.37,68.7
12V0_FILTERED_PS_V5V0 on BOTTOM (solid shape): 113.69,82.6 113.69,81.53 113.68,81.47 113.67,81.42 113.68,81.38 113.69,81.32 113.69,81.25 113.98,80.96 115.26,80.96 115.97,80.25 118.49,80.25 118.88,79.86 118.88,78.07 118.52,77.71 113.5,77.71 112.92,78.28 112.92,81.46 112.62,81.76 112.62,82.55 112.72,82.66 113.63,82.66
12V0_FILTERED_PS_V5V0 on TOP: 112.62,82.55 112.62,81.7 112.92,81.39 112.92,78.28 113.5,77.71 118.52,77.71 118.88,78.07 118.88,79.86 118.49,80.25 115.97,80.25 115.26,80.96 113.79,80.96 113.46,81.3 113.46,82.6 113.4,82.66 112.72,82.66 112.62,82.55
12V0_IN on TOP: 120.61,112.56 129.17,112.56 129.22,112.51 129.22,105.33 129.09,105.2 128.79,105.2 128.72,105.26 128.66,105.2 125.16,105.2 125.03,105.33 125.03,107.61 124.78,107.87 122.39,107.87 120.61,107.84
12V0_IN on BOTTOM: 120.61,112.62 129.17,112.62 129.22,112.56 129.22,105.38 129.09,105.25 128.79,105.25 128.72,105.31 128.66,105.25 125.16,105.25 125.03,105.38 125.03,107.66 124.78,107.92 122.39,107.92 120.61,107.89
12V0_IN_GND on TOP, BOTTOM: 120.32,120.23 120.32,115.69 120.39,115.62 120.39,113.12 129.45,113.12 129.7,112.87 129.7,112.54 129.86,112.39 129.86,104.41 124.84,104.41 124.81,104.39 124.81,103.98 124.83,103.96 124.83,102.53 124.8,102.51 124.8,99.41 131.43,99.41 131.86,99.84 131.86,119.85 131.47,120.23
12V0_PS_F on TOP: 120.76,107.36 123.91,107.36 123.99,107.28 123.99,100.04 123.45,99.51 115.28,99.51 114.77,100.02 114.77,106.88 114.74,106.9 120.3,106.9
12V0_PS_F on BOTTOM: 120.74,107.36 123.89,107.36 123.96,107.28 123.96,100.04 123.43,99.51 115.25,99.51 114.74,100.02 114.74,106.88 114.72,106.9 120.28,106.9
AVDD_CGA1 on L4_INT_2: 69.96,49.08 69.96,48.39 70.67,48.39 71.1,48.82 78.34,48.82 78.34,50.06 70.93,50.06
AVDD_CGA2 on L4_INT_2: 69.71,49.61 69.71,45.98 69.94,45.74 74.81,45.74 75.62,46.56 78.57,46.56 78.79,46.34 78.78,46.33 78.78,44.26 75.79,44.26 75.11,43.58 66.25,43.58 64.98,44.85 64.98,46.64 65.91,47.57 67.18,47.57 69.22,49.61
AVDD_DDR1 on BOTTOM: 85.58,37.74 88.38,37.74 88.51,37.61 88.51,35.96 88.42,35.87 85.41,35.87 85.33,35.96 85.33,37.48
AVDD_DDR1 on L4_INT_2: 63.61,42.28 63.82,42.49 69.36,42.49 71.77,40.08 80.05,40.08 80.58,39.55 80.6,39.55 80.6,39.54 81.06,39.08 85.63,39.08 86.85,37.86 86.85,36.34 86.47,35.96 85.71,35.96 85.08,36.59 85.08,37.74 84.95,37.86 81.52,37.86 81.14,37.48 81.14,37.24 80.78,36.89 75.8,36.89 75.29,37.39 70.98,37.39 69.79,38.58 63.84,38.58 63.61,38.81
AVDD_PLAT on L4_INT_2: 69.73,50.14 69.73,51.29 69.98,51.54 77.4,51.54 77.81,51.95 77.81,52.39 78.14,52.72 78.78,52.72 79.21,52.29 79.21,50.54 79.02,50.35 70.72,50.35 70.36,49.99 69.88,49.99
AVDD_SRDS1_PLL1 on TOP: 53.01,50.85 53.01,49.99 52.69,49.67 48.75,49.67 48.63,49.8 48.63,50.82 48.88,51.07 52.78,51.07
AVDD_SRDS1_PLL1 on L3_INT_1: 49.09,49.97 49.09,50.56 49.35,50.82 50.28,50.82 51.14,49.96 58.76,49.96 59.39,49.32 59.39,48.28 59.42,48.25 59.42,48 59.6,47.82 59.6,47.21 51.83,47.21 51.36,47.68 51.36,47.7
AVDD_SRDS1_PLL2 on TOP: 48.25,54.63 48.25,55.77 48.5,56.02 51.17,56.02 52.44,54.75 52.44,54.37 52.31,54.25 51.29,54.25 51.17,54.12 49.52,54.12 49.39,54.25 48.63,54.25
AVDD_SRDS1_PLL2 on L3_INT_1: 53.38,52.98 58.41,52.98 58.66,52.72 58.66,50.82 58.28,50.44 51.67,50.44 48.7,53.41 48.7,54.88 49.12,55.3 50.37,55.3 50.46,55.2 51.15,55.2
AVDD_SRDS2_PLL1 on TOP: 45.2,47.39 50.15,47.39 50.28,47.52 50.28,48.02 49.77,48.53 45.58,48.53 45.2,48.15
AVDD_SRDS2_PLL1 on L3_INT_1: 47.99,45.11 45.83,47.26 45.83,48.28 46.21,48.66 49.26,48.66 51.12,46.8 51.13,46.8 51.4,46.54 59.57,46.54 59.57,45.24 59.44,45.11
AVDD_SRDS2_PLL2 on TOP: 45.2,44.21 46.47,44.21 46.72,44.47 49.01,44.47 49.39,44.09 49.39,43.32 49.26,43.2 45.2,43.2 44.94,43.45 44.94,43.96
AVDD_SRDS2_PLL2 on L3_INT_1: 59.53,43.49 55.66,39.61 47.13,39.61 45.71,41.04 45.71,43.83 46.05,44.18 51.42,44.18 51.84,44.59 54.98,44.59 55.1,44.72 59.37,44.72 59.53,44.56
GND on TOP (solid shape): 115.35,98.24 115.35,96.05 115.02,95.72 110.02,95.72 109.92,95.62 109.92,94.02 110.25,93.69 110.96,93.69 111.31,93.34 111.31,92.17 111.29,92.14 110.63,92.14 110.37,92.4 110.11,92.4 110.1,92.41 110.05,92.46 109.99,92.47 109.79,92.47 109.73,92.46 109.68,92.41 109.67,92.4 109.43,92.4 109.43,96.77 109.51,96.84 109.51,96.99 109.97,96.99 109.98,96.98 109.99,96.99 112.84,96.99 112.84,97.86 112.98,98 112.98,98.38 113.12,98.52 115.07,98.52
GND on TOP (solid shape): 108.65,97.93 108.65,95.75 108.32,95.42 103.31,95.42 103.21,95.32 103.21,93.72 103.54,93.39 104.33,93.39 104.61,93.11 104.61,91.86 104.58,91.84 103.92,91.84 103.67,92.09 103.36,92.09 103.35,92.12 103.31,92.17 103.24,92.19 103.03,92.19 102.96,92.17 102.91,92.12 102.91,92.09 102.73,92.09 102.73,96.46 102.8,96.54 102.8,96.69 103.26,96.69 103.27,96.68 103.29,96.69 106.13,96.69 106.13,97.55 106.27,97.69 106.27,98.07 106.41,98.21 108.37,98.21
GND on TOP: 118.54,42.6 119.14,43.2 119.14,44.26 119.03,44.37 117.21,44.37 117.19,44.35 117.14,44.35 113.93,41.14 109.92,41.14 109.71,40.94 109.71,34.98 110.13,34.56 114.59,34.56 116.6,32.54 116.6,32.53 123.68,32.53 123.94,32.78 123.94,33.93 123.56,34.31 119.87,34.31 119.75,34.43 119.75,36.85 118.35,38.24 118.35,42.18 118.54,42.37
GND on TOP: 100.75,76.55 100.75,72.08 100.9,71.92 102.63,71.92 102.88,72.18 102.88,73.4 101.89,74.39 101.89,75.94 101.86,75.94 101.43,76.37 101.43,76.65 100.85,76.65
GND on TOP: 96.07,32.91 96.07,31.06 101.28,31.06 101.28,32.91
GND on TOP: 85.93,51 85.74,50.82 85.74,46.5 85.87,46.37 91.9,46.37 92.07,46.54 92.07,50.77 91.84,51
GND on TOP: 84.47,81.93 84.47,69.21 84.72,68.95 85.79,68.95 86.57,69.74 86.57,82.26 85.63,83.2 79.51,83.2 79.16,82.85 77.94,82.85 77.61,82.52 77.61,81.17 77.66,81.12 79.33,81.12 79.56,81.35 79.56,81.78 80.38,82.59 84.16,82.59 84.52,82.24 84.52,81.98
GND on TOP: 74.89,69.92 74.56,70.25 72.1,70.25 71.82,69.97 71.82,68.24 71.71,68.14 70.01,68.14 70.04,68.17 70.04,70.07 69.89,70.22 69.2,70.22 68.97,70.45 68.97,70.91 68.74,71.14 66.71,71.14 66.53,70.96 66.53,70.4 66.66,70.27 67.6,70.27 67.73,70.15 67.73,69.23 67.85,69.11 67.88,69.11 69.05,67.94 69.05,67.51 69.3,67.25 74.48,67.25 74.89,67.66
GND on TOP: 31.05,50.71 31.05,47.83 30.96,47.74 29.34,47.74 29.12,47.96 29.12,50.54 29.45,50.86 30.9,50.86
GND on TOP: 34.8,19.06 34.8,16.97 34.92,16.85 36.42,16.85 36.57,17 36.57,18.97 36.11,19.43 35.17,19.43
GND on TOP: 49.9,83.79 49.91,83.77 49.91,83.47 49.95,83.43 51.95,83.43 52.18,83.2 52.18,75.94 52.33,75.79 53.68,75.79 53.86,75.96 53.86,88.99 53.73,89.12 52,89.12 51.88,88.99 51.88,84.57 51.8,84.5 50,84.5 49.9,84.4
GND on TOP: 84.01,116.3 84.01,114.83 84.34,114.5 89.7,114.5 90,114.8 90,116.3 89.77,116.53 84.24,116.53
GND on TOP: 32.88,71.77 29.47,71.77 29.07,72.18 29.07,85.67 29.69,86.3 31.32,86.3 31.63,85.98 31.63,79.24 31.96,78.92 31.96,77.24 31.63,76.92 31.63,75.86 32.02,75.47 32.96,75.47 33.17,75.27 33.17,72.06
GND on TOP: 98.84,81.63 101.56,81.63 102.19,80.99 102.19,78.12 102.14,78.07 100.92,78.07 100.57,78.43 100.57,79.27 100.49,79.34 98.92,79.34 98.64,79.62 98.64,81.42
GND on TOP: 32.34,45.99 32.34,45.38 32.7,45.02 34.75,45.02 35.21,45.48 35.21,45.9 35,46.1 32.46,46.1
GND on TOP: 77.53,115.33 77.49,115.3 77.49,114.37 77.39,114.27 76.34,114.27 76.31,114.29 76.31,115.23 76.21,115.33 76.21,118.18 76.06,118.33 76.06,119.4 76.19,119.52 77.46,119.52 77.58,119.4 77.58,118.05 77.53,118
GND on TOP: 118.68,19.5 120.05,19.5 120.05,21.63 119.75,21.94 118.07,21.94 117.94,21.81 117.94,21.25 118.68,20.52
GND on TOP: 123.99,10.31 126.83,10.31 127.03,10.52 127.03,11.65 126.75,11.93 124.96,11.93 123.93,10.9 123.93,10.37
GND on TOP: 14.34,32.68 14.34,7.48 14.46,7.36 33.6,7.36 33.84,7.6 33.84,32.62 33.63,32.83 14.49,32.83
GND on TOP: 46.72,46.88 49.77,46.88 50.53,46.12 50.53,45.1 50.15,44.72 49.26,44.72 49.13,44.85 48.5,44.85 48.37,44.72 47.86,44.72 47.61,44.98 46.59,44.98 46.47,45.1 46.47,46.63
GND on TOP: 39.99,112.16 40.75,111.4 41.31,111.4 41.31,110.53 41.51,110.33 44.08,110.33 44.31,110.56 44.31,111.27 44.94,111.9 44.94,114.83 44.69,115.08 40.37,115.08 39.99,114.7
GND on TOP: 50.15,53.48 51.29,53.48 51.67,53.87 52.69,53.87 52.94,53.61 52.94,51.83 52.56,51.45 50.15,51.45 50.02,51.58 50.02,53.36
GND on TOP: 45.55,61.48 45.55,59.86 48.63,59.86 48.63,61.48
GND on TOP: outline of 92 points within 106.3,61.86 131.85,98.52 ; 2 cut-outs
GND on TOP: 116.95,10.69 116.95,11.96 115.43,13.48 114.29,13.48 113.9,13.1 113.9,10.69
GND on TOP: 18.02,44.56 18.02,43.59 17.8,43.37 17.8,43.35 17.19,43.35 17.09,43.25 17.09,41.62 16.7,41.62 16.7,43.22 16.57,43.35 15.67,43.35 15.59,43.28 15.59,41.64 15.56,41.62 15.05,41.62 15.05,43.07 14.92,43.19 13.84,43.19 13.64,43.39 13.64,44.46 13.9,44.72 16.16,44.72 16.2,44.76 17.82,44.76
GND on TOP: 57.19,85.31 57.19,85.87 56.88,86.17 55.33,86.17 54.72,85.56 54.72,72.5 55.07,72.15 57.34,72.15 57.49,72.31 57.49,85.01
GND on TOP: 103.08,77.56 103.08,76.5 104.3,76.5 104.3,77.06 103.79,77.56
GND on TOP: 38.09,26.31 36.05,26.31 35.67,25.93 35.67,23.39 36.31,22.75 37.7,22.75 38.09,23.13
GND on TOP: 118.48,52.09 118.48,49.27 118.54,49.2 118.54,48.32 119.19,47.67 119.19,46.47 119.06,46.35 117.23,46.35 114.31,49.27 109.73,49.27 109.71,49.29 109.71,56.02 109.97,56.28 116.95,56.28 117.46,55.77 117.46,53.11
GND on TOP: 35.9,34.11 35.9,32.63 36.08,32.45 40.52,32.45 40.75,32.68 40.75,34.26 40.71,34.3 36.1,34.3
GND on TOP, BOTTOM: 86.85,33.49 86.85,31.61 92.44,31.61 92.44,33.49
GND on BOTTOM: 95.54,116.65 95.54,115.03 95.87,114.7 101.56,114.7 101.79,114.93 101.79,116.48 101.46,116.81 95.69,116.81
GND on BOTTOM: 71.48,66.12 71.48,64.51 74.38,64.51 74.38,64.51 75.38,64.51 75.38,66.12
GND on BOTTOM: 77.61,118.94 77.28,118.61 77.28,115.92 77.12,115.77 76.31,115.77 76.16,115.92 76.16,119.55 76.19,119.58 77.61,119.58
GND on BOTTOM: 115.43,13.48 116.57,12.34 116.57,11.07 114.29,11.07 113.78,11.57 113.78,13.35 113.9,13.48
GND on BOTTOM: 39.36,37.86 37.83,37.86 37.58,38.12 37.58,40.78 37.86,41.06 39.1,41.06 39.35,40.82 39.35,38.73 39.36,38.71 39.36,37.86
GND on BOTTOM: 118.46,52.06 118.46,49.24 118.53,49.18 118.53,48.29 119.17,47.64 119.17,46.45 119.05,46.32 117.22,46.32 114.29,49.24 109.72,49.24 109.7,49.26 109.7,56 109.95,56.25 116.94,56.25 117.45,55.74 117.45,53.08
GND on BOTTOM: 33.72,80.36 34.25,80.89 34.25,82.31 34.48,82.54 37.83,82.54 38.09,82.29 38.09,78 38.02,77.93 38.02,76.03 37.7,75.71 37.7,74.47 37.26,74.02 37.26,72.26 37.89,71.62 42.95,71.62 42.95,71.59 43.6,70.94 44.63,70.94 44.64,70.92 44.64,70.12 44.38,69.87 36.07,69.87 35.12,70.82 35.12,78.78 34.1,79.8 32.07,79.8 31.94,79.67 31.94,77.06 31.96,77.03 31.68,76.75 30.49,76.75 30.03,77.21 30.03,86.43 30.44,86.83 31.89,86.83 31.89,80.77 32.09,80.57 32.09,80.54 32.27,80.36
GND on BOTTOM: 105.9,32.63 105.9,29.76 106.23,29.43 107.53,29.43 107.67,29.58 107.67,32.44 107.15,32.96 106.23,32.96
GND on BOTTOM: 79.54,45.43 79.54,43.73 81.37,43.73 81.37,45.43
GND on BOTTOM: 85.75,51.07 91.53,51.07 92.26,50.34 92.26,47.79 91.96,47.49 86.2,47.49 85.54,48.15 85.54,50.86
GND on BOTTOM: 102.35,77.97 102.35,76.5 104.3,76.5 104.3,77.97
GND on BOTTOM: 35.95,34.33 40.55,34.33 40.7,34.18 40.7,32.66 40.57,32.53 35.98,32.53 35.9,32.61 35.9,34.28
GND on BOTTOM: 106.26,98.14 107.33,98.14 108.65,96.82 112.89,96.82 112.9,96.83 112.9,98.58 113.02,98.7 114.62,98.7 115.33,97.99 115.33,95.6 115.17,95.45 103.36,95.45 103.13,95.67 103.13,96.33 103.31,96.51 106.16,96.51 106.26,96.61
GND on BOTTOM: 63.46,62.86 61.99,62.86 61.81,62.68 61.81,62.25 61.96,62.09 63.03,62.09 63.21,61.92 63.21,60.37 63.54,60.04 64.12,60.04 64.32,60.24 64.32,61.23 63.71,61.84 63.71,62.6
GND on BOTTOM: 20.03,104.11 18.07,104.11 17.82,104.36 17.82,104.97 18.86,106.01 18.86,111.78 18.93,111.85 20.05,111.85 20.1,111.8 20.1,104.18
GND on BOTTOM: 28.85,67.11 28.93,67.03 28.93,63.27 28.48,62.83 24.8,62.83 24.8,66.27 22.69,66.27 22.69,63.27 22.64,63.27 22.64,62.61 22.41,62.38 21.72,62.38 21.61,62.5 21.61,62.83 21.57,62.87 21.57,63.27 21.49,63.27 21.49,67.06 21.54,67.11
GND on BOTTOM: 64.5,62.12 65.57,62.12 65.77,61.92 65.77,58.72 66.18,58.31 67.55,58.31 67.88,58.64 67.88,59.17 67.75,59.3 67.75,61.97 67.9,62.12 69.01,62.12 69.01,62.64 68.71,62.93 64.5,62.93 64.44,62.87 64.42,62.87 64.42,62.2
GND on BOTTOM: 64.96,90.87 65.03,90.8 65.64,90.8 66.16,91.32 67.4,91.32 67.6,91.52 67.6,91.76 67.6,91.76 67.6,95.09 68.06,95.55 69.96,95.55 70.52,96.11 70.52,97.78 70.11,98.19 67.85,98.19 67.63,97.96 66,97.96 65.92,98.04 65.92,98.42 65.67,98.67 64.96,98.67
GND on BOTTOM: 123.99,10.31 128.11,10.31 128.42,10.62 128.42,11.84 128.28,11.98 124.25,11.98 123.88,11.61 123.88,10.42
GND on BOTTOM: 14.34,43.26 14.34,17.03 33.84,17.03 33.84,42.36 32.94,43.26
GND on BOTTOM: 100.7,76.62 100.7,71.92 102.63,71.92 102.88,72.18 102.88,73.4 102.07,74.21 102.07,75.63 101.99,75.71 101.99,75.81 101.43,76.37 101.43,76.62
GND on BOTTOM: 96.02,25.98 96.07,25.93 100.67,25.93 101.18,26.43 101.18,30.62 100.7,31.11 98.99,31.11 98.94,31.06 96.33,31.06 96,31.39 96,32.53 96.63,33.16 101.1,33.16 102.63,31.64 102.63,25.47 101.41,24.25 96.23,24.25 96.02,24.45
GND on BOTTOM: 109.03,15.23 109.03,2.3 111.19,2.3 111.19,15.23
GND on BOTTOM: 110.58,62.07 110.46,62.19 110.46,76.74 109.34,77.86 105.86,77.86 105.19,78.53 105.19,84.62 105.67,85.11 110.84,85.11 111.04,85.31 111.04,88.5 112.02,89.48 114.74,89.48 121.07,83.15 121.07,82.74 121.11,82.7 121.11,76.82 121.51,76.42 129.19,76.42 129.61,76.85 129.61,78.54 128.9,79.25 128.9,81.95 128.41,82.44 125.97,82.44 125.97,91.41 125.92,91.46 124.56,91.46 124.38,91.64 124.38,98.65 124.41,98.62 131.87,98.62 131.9,98.59 131.9,62.15 131.82,62.07 ; 2 cut-outs
GND on BOTTOM: 68.01,80.87 73.47,80.87 74.25,80.08 74.25,75.56 74.48,75.33 74.48,74.06 74.41,73.98 68.29,73.98 67.5,74.77 67.5,80.36
GND on BOTTOM: 84.43,58.64 84.43,58.38 83.89,57.84 83.89,56.57 84.16,56.3 86.71,56.3 87.1,56.68 89.51,56.68 89.68,56.85 91.43,56.85 92.08,57.5 92.08,58.4 92.07,58.41 92.07,58.5 91.64,58.94 90.73,58.94 89.5,57.71 89.5,57.7 89.01,57.7 88.45,58.27 88.45,59.31 88.04,59.71 87.44,59.71 87.42,59.69 87.14,59.97 87.14,60.38 86.92,60.6 85.96,60.6 85.72,60.36 85.72,58.76 85.65,58.68 84.47,58.68
GND on BOTTOM: 118.53,42.57 119.12,43.17 119.12,44.24 119.02,44.34 117.19,44.34 117.18,44.32 117.13,44.32 113.92,41.12 110.21,41.12 109.7,40.61 109.7,34.53 111.73,32.5 123.67,32.5 123.92,32.75 123.92,33.9 123.54,34.28 119.86,34.28 119.73,34.41 119.73,36.82 118.33,38.22 118.33,42.15 118.53,42.34
GND on L2_GND: 90.24,120.41 131.94,120.41 131.94,39.55 131.94,39.55 131.94,34.26 131.94,34.26 131.94,1.65 123.94,1.65 123.94,5.88 123.43,5.88 123,6.32 114.92,6.32 114.54,5.94 114.54,1.67 114.52,1.65 94.26,1.65 94.26,1.65 93.65,1.65 93.65,1.65 13.21,1.65 13.21,120.41 28.43,120.41 53.23,120.41 61.32,120.41 67.55,120.41 71.32,120.41
GND on L5_PWR: outline of 97 points within 13.83,2.05 114.04,70.57
GND on L5_PWR: 99.2,115.03 106,115.03 113.9,107.13 113.9,102.58 110.5,99.18 103.97,99.18 102.4,97.61 102.4,92 101.89,91.48 99.2,91.48 98.89,91.18 98.89,84.17 95.15,80.42 95.15,74.81 77.23,56.89 77.23,51.71 77.09,51.57 69.86,51.57 69.76,51.68 69.76,55.11 70.04,55.4 70.04,55.87 89.34,75.16 89.34,76.42 89.82,76.9 89.82,79.93 89.6,80.15 87.69,80.15 86.62,81.22 86.62,83.35 87.44,84.17 90.33,84.17 92.47,86.3 92.47,87.67 92.44,87.7 92.44,92.07 92.43,92.08 92.43,92.79 92.38,92.84 92.38,94.98 93.73,96.33 93.73,109.56
GND_EARTH on TOP: 73.39,120.16 74.66,121.43 87.74,121.43 88.63,120.54 89.7,120.54 90.03,120.21 90.03,119.3 107.15,119.3 112.96,113.48 112.96,102.68 111.75,101.46 109.99,101.46 109.36,102.1 109.36,110.86 108.39,111.83 99.98,111.83 99.68,111.52 99.68,102.58 98.28,101.19 96.56,101.19 95.44,102.3 95.44,115.21 94.32,116.32 90.82,116.32 89.52,117.62 84.44,117.62 84.31,117.49 84.31,117.47 83.17,116.32 80.76,116.32 80.25,116.83 80.25,119.27 79.36,120.16 76.31,120.16 75.3,119.14 75.3,117.09 74.53,116.32 67.7,116.32 67.7,101.57 65.52,99.38 62.06,99.38 61.66,99.79 61.66,102.56 62.29,103.19 65.26,103.19 65.34,103.12 66.03,103.8 66.03,116.21 46.87,116.21 46.27,115.61 40.65,115.61 40.65,115.62 39.05,115.62 37.51,117.16 25.01,117.16 22.51,114.65 22.51,111.97 24.39,110.08 24.39,99.35 21.49,99.35 21.49,112.66 20.93,113.22 15.11,113.22 13.88,114.45 13.88,118 14.95,119.07 18.37,119.07 18.43,119.12 18.74,119.12 19.02,119.4 19.16,119.4 19.18,119.38 24.45,119.38 24.47,119.4 32.37,119.4 32.37,120.16
GND_EARTH on TOP: 117.08,9.67 117.21,9.54 117.21,8.78 116.83,8.4 115.56,8.4 115.56,7.38 114.65,6.48 114.65,0.78 114.53,0.65 113.52,0.65 113.27,0.91 113.27,1.16 112.63,1.8 112.63,2.3 113.27,2.94 113.27,9.54 113.4,9.67
GND_EARTH on BOTTOM: 61.45,119.78 71.61,119.78 71.99,119.78 72.88,120.67 72.88,121.56 74.38,121.56 74.38,119.4 73.77,119.4 73.26,118.89 73.26,108.86 73.39,108.86 73.26,108.73 73.26,108.35 73.52,108.09 75.93,108.09 75.93,105.68 79.61,105.68 79.87,105.94 79.87,108.09 80.12,108.35 81.9,108.35 81.9,105.17 81.35,104.63 73.96,104.63 71.89,106.7 71.89,116.73 71.16,117.47 61.45,117.47
GND_EARTH on BOTTOM: 125.85,5.58 125.77,5.5 125.77,1.95 125.73,1.91 125.73,1.55 124.83,0.65 124.06,0.65 123.94,0.78 123.94,6.62 123.81,6.75 123.66,6.75 123.15,7.26 123.15,8.42 123.4,8.67 124.7,8.67 125.85,7.52
GND_EARTH on BOTTOM: 84.16,117.59 89.72,117.59 90.03,117.9 90.03,120.21 89.74,120.5 88.67,120.5 88.63,120.54 87.87,120.54 87.62,120.79 87.62,122.06 87.23,122.45 86.22,122.45 84.44,120.67 84.38,120.67 83.93,120.21 83.93,117.82
GND_EARTH on BOTTOM: 95.36,119.78 101.81,119.78 101.81,118.03 101.66,117.87 95.64,117.87 95.36,118.15
GND_EARTH on BOTTOM: 115.21,8.06 114.54,7.38 114.54,0.91 114.29,0.65 113.65,0.65 113.14,1.16 113.14,9.54 113.27,9.67 117.21,9.67 117.59,9.29 117.59,8.4 117.33,8.15 117.21,8.15 117.12,8.06
GND_EARTH on L3_INT_1: 111.02,101.16 113.45,101.16 122.49,92.12 122.49,85.97 127.6,80.86 127.6,10.69 127.1,10.18 125.59,10.18 125.33,9.92 125.33,2.05 125.59,1.8 125.59,1.78 130.6,1.78 131.83,3.01 131.83,91.21 117.05,105.99 110.93,105.99 110.55,105.61 110.55,101.62
GND_EARTH on L3_INT_1: 42.81,104.77 40.07,104.77 38.24,102.94 38.24,100.04 38.72,99.56 46.49,99.56 47.76,100.83 47.76,103.4 46.82,104.34 46.82,116.73 47.38,117.29 47.38,118.08 46.57,118.89 39,118.89 38.42,118.31 38.42,116.48 39.02,115.87 42.48,115.87 44.36,113.99 44.36,106.7 43.67,106.01 43.67,105.63
GND_EARTH on L4_INT_2: 130.07,7.89 130.98,7.89 131.61,7.26 131.59,7.24 131.59,2.78 130.61,1.8 125.97,1.8 124.82,0.65 124.45,0.65 124.06,1.03 124.06,5.1 123.69,6 122.79,6.37 116.32,6.37 115.72,6.34 115.17,6.11 114.67,5.57 114.48,4.84 114.48,0.85 114.41,0.78 113.71,0.78 112.63,1.85 14.23,1.85 13.3,2.79 13.3,5.98 14.84,7.51 18.35,7.51 22.76,3.1 111.02,3.1 112.32,4.4 112.32,8.17 129.79,8.17
V3V3_SW on TOP: 117.8,67.54 117.8,66.4 115.73,64.33 115.73,62.85 116.1,62.48 121.49,62.48 121.78,62.77 121.78,64.41 120.11,66.08 120.11,67.43 119.99,67.55 119.99,67.55 117.82,67.55
V5V0_SW on TOP: 106.79,84.88 106.79,83.57 106.96,83.4 110.61,83.4 110.93,83.71 112.51,83.71 112.58,83.78 112.58,84.42 112.5,84.51 111.74,84.51 111.73,84.49 111.07,84.49 110.64,84.92 106.84,84.92 106.8,84.88
VCC_USB1_PWR on TOP (solid shape): 114.74,95.29 115.28,95.29 115.35,95.22 115.35,93.59 115.33,93.57 112.15,93.57 112.13,93.54 112.13,92.93 111.8,92.93 111.77,92.91 111.77,92.8 111.75,92.73 111.74,92.67 111.74,92.53 111.52,92.53 111.52,93.42 111.52,93.57 111.16,93.92 110.35,93.92 110.25,94.02 110.25,95.32 114.72,95.32
VCC_USB1_PWR on BOTTOM: 110.25,95.32 114.72,95.32 114.74,95.29 115.28,95.29 115.35,95.22 115.35,93.59 115.33,93.57 115,93.57 114.92,93.64 114.92,93.59 114.89,93.57 112.15,93.57 112.13,93.54 112.13,92.93 111.8,92.93 111.77,92.91 111.77,92.5 111.75,92.47 111.47,92.47 111.41,92.52 111.41,93.54 111.03,93.92 110.35,93.92 110.25,94.02
VCC_USB2_PWR on TOP (solid shape): 108.04,94.99 108.57,94.99 108.65,94.91 108.65,93.29 108.62,93.26 108.29,93.26 108.25,93.3 108.21,93.29 108.19,93.26 105.45,93.26 105.42,93.24 105.42,92.68 105.4,92.65 105.06,92.65 105.04,92.63 105.04,92.43 105.03,92.37 105.03,92.22 104.86,92.22 104.86,93.21 104.43,93.64 103.65,93.64 103.54,93.75 103.54,95.01 108.01,95.01
VCC_USB2_PWR on BOTTOM: 103.54,95.01 108.01,95.01 108.04,94.99 108.57,94.99 108.65,94.91 108.65,93.29 108.62,93.26 108.29,93.26 108.21,93.34 108.21,93.29 108.19,93.26 105.45,93.26 105.42,93.24 105.42,92.63 105.09,92.63 105.06,92.6 105.06,92.19 105.04,92.17 104.76,92.17 104.71,92.22 104.71,93.24 104.33,93.62 103.64,93.62 103.54,93.72
VDD_CLKOUT on BOTTOM: 23.09,65.79 23.09,62.74 22.48,62.13 22.48,61.24 22.61,61.11 30.61,61.11 30.79,61.29 30.79,64.21 30.46,64.54 29.39,64.54 29.32,64.47 29.32,62.71 28.95,62.35 24.51,62.35 24.29,62.57 24.29,66.12 24.21,66.19 23.5,66.19
VDD_SI5332 on BOTTOM: 28.91,67.67 29.16,67.92 29.16,70.54 22.81,70.54 22.64,70.36 22.64,68.86 22.48,68.71 22.48,67.79 22.61,67.67
VDD_SW on TOP: 120.71,44.75 120.79,44.82 120.79,45.84 120.66,45.97 116.85,45.97 114.29,48.53 110.85,48.53 110.85,41.65 113.85,41.65 116.94,44.75
VDDO7 on BOTTOM: 29.49,66.53 31.11,66.53 31.46,66.88 31.46,68.72 29.98,68.72 29.49,68.24
(no net) on TOP: 103.54,95.01 108.01,95.01 108.04,94.99 108.57,94.99 108.65,94.91 108.65,93.29 108.62,93.26 108.29,93.26 108.21,93.34 108.21,93.29 108.19,93.26 105.45,93.26 105.42,93.24 105.42,92.68 105.4,92.65 105.06,92.65 105.04,92.63 105.04,92.17 104.76,92.17 104.71,92.22 104.71,93.24 104.33,93.62 103.64,93.62 103.54,93.72
(no net) on TOP: 108.32,95.42 108.65,95.75 108.65,97.93 108.37,98.21 106.41,98.21 106.27,98.07 106.27,97.69 106.13,97.55 106.13,96.69 103.29,96.69 103.27,96.68 103.26,96.69 102.8,96.69 102.8,96.54 102.73,96.46 102.73,92.09 103.67,92.09 103.92,91.84 104.58,91.84 104.61,91.86 104.61,93.11 104.33,93.39 103.54,93.39 103.21,93.72 103.21,95.32 103.31,95.42
